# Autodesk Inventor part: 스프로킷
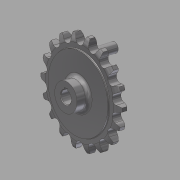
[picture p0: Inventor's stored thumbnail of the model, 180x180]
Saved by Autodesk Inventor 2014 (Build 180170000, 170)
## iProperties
Created: 2016-03
Part Number: 스프로킷
Material: 강철, 탄소
Document SubType Name: Modeling
Designer: mduedu
Density: 7.87 g/cm^3
Mass: 309.171 g
Surface Area: 126.546 cm^2
Volume: 39.2847 cm^3
Appearance: 반광택
Author: mduedu
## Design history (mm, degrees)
sketch "스케치1"
  geometry: L1 (0, 5)-(29.5, 5); L2 (29.5, 5)-(29.5, 4.1); L3 (30, 3.6)-(33.625, 3.6); L4 (40, 2)-(40, 0); L5 (40, 0)-(0, 0); L6 (0, 0)-(0, 5); L7 (0, -5)-(29.5, -5); L8 (29.5, -5)-(29.5, -4.1); L9 (30, -3.6)-(33.625, -3.6); L10 (40, -2)-(40, 0); L11 (0, 0)-(0, -5); A1 r 13.5 centre (33.625, -9.9) between (40, 2) and (33.625, 3.6); A2 r 13.5 centre (33.625, 9.9) between (33.625, -3.6) and (40, -2); A3 r 0.5 centre (30, 4.1) between (29.5, 4.1) and (30, 3.6); A4 r 0.5 centre (30, -4.1) between (30, -3.6) and (29.5, -4.1); 2 further points
  constraints: 22 end point, 8 point on circle, 6 symmetric about line, 5 tangent, 4 centre point, 4 parallel, 4 point on line, 1 equal radius, 1 horizontal, 1 perpendicular, 1 other
  dimensions: "d0" = 80 diameter of L4 L6; "d2" = 59 diameter of L2 L6; "d3" = 1.6 vertical distance of L4.start L3.end; "d4" = 3.6 distance from line of L4.end L3; "d5" = 5 distance between parallel lines of L5 L1; "d6" = 13.5 radius of A1; "d15" = 0.5 radius of A3
revolve "회전1" sketch "스케치1" stored, may be unused: angle "d7" = 90 deg
sketch "스케치2" dims "d8" = 65.2, "d11" = 80
  geometry: L1 (0, 0)-(0, 32.6); A1 r 36.57 centre (0, 0) between (-16.231, 32.771) and (0, 36.57); A2 r 3.97 centre (0, 36.57) between (-3.866, 35.665) and (0, 32.6); A3 r 12.7 centre (-16.231, 32.771) between (-3.866, 35.665) and (-5.534, 39.615); A4 r 12.7 centre (16.231, 32.771) between (5.534, 39.615) and (3.866, 35.665); A5 r 3.97 centre (0, 36.57) between (0, 32.6) and (3.866, 35.665); A6 r 40 centre (0, 0) between (5.534, 39.615) and (-5.534, 39.615); 2 further points
  constraints: 12 point on circle, 6 centre point, 4 coincident, 3 symmetric about line, 2 end point, 1 point on line, 1 tangent, 1 vertical, 1 vertical alignment, 7 other
  dimensions: "d10" = 73.14 diameter of A1; "d12" = 12.7 radius of A3
extrude "돌출1" cut sketch "스케치2" stored distance "d13" = 10; taper "d14" = 0 deg
sketch "스케치3"
  geometry: C1 r 11 at (0, 0); 1 further point
  constraints: 1 centre point, 1 coincident
  dimensions: "d19" = 22 diameter of C1
extrude "돌출2" join sketch "스케치3" distance "d20" = 10; taper "d21" = 0 deg
fillet "모깎기1" dims "d22" = 3
sketch "스케치4"
  geometry: L1 (-1.5, 0)-(1.5, 0); L2 (1.5, 0)-(1.5, 6.4); L3 (1.5, 6.4)-(-1.5, 6.4); L4 (-1.5, 6.4)-(-1.5, 0); C1 r 5 at (0, 0); 2 further points
  constraints: 8 end point, 2 coincident, 2 parallel, 1 centre point, 1 horizontal, 1 midpoint, 1 perpendicular
  dimensions: "d23" = 10 diameter of C1; "d25" = 3 distance of L2.end L3.end; "d26" = 6.4 distance of L1.end L2.end
extrude "돌출3" cut sketch "스케치4" stored distance "d27" = 8; taper "d28" = 0 deg
chamfer "모따기1" distance "d29" = 0.5; stored, may be unused: second distance "d30" = 2, angle "d31" = 45 deg
sketch "스케치5" dims "d33" = 48
  geometry: C1 r 4 at (0, 24); 2 further points
  constraints: 2 vertical alignment, 1 centre point, 1 coincident, 2 other
  dimensions: "d32" = 8 diameter of C1
extrude "돌출4" join sketch "스케치5" distance "d34" = 20; taper "d35" = 0 deg
fillet "모깎기2" dims "d36" = 1
hole "구멍1" diameter "d39" = 3.242; stored, may be unused: countersink angle "d43" = 90 deg, drill point angle "d45" = 118 deg; dims "d40" = 8, "d41" = 4, "d42" = 2, "d44" = 10, "d46" = 10, "d47" = 10
node "솔리드1"
pattern_circular "원형 패턴1" dims angle "d17" = 360 deg
